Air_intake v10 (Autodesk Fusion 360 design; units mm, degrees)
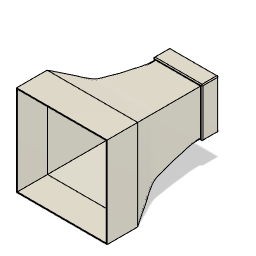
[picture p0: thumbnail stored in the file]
sketch "Sketch1" plane through (0, 0, 0) normal (0, 0, 1) x axis (1, 0, 0)
  line L1 (-150, 150) -> (150, 150)
  line L2 (-150, -150) -> (-150, 150)
  line L3 (150, -150) -> (-150, -150)
  line L4 (150, 150) -> (150, -150)
  line L5 (-150, -150) -> (150, 150)
  line L6 (150, -150) -> (-150, 150)
  point P6 (0, 0)
  point P1 (0, 0)
  point P4 (-150, -150)
  point P5 (150, -150)
  point P3 (-150, 150)
  horizontal L1
  perpendicular L1 L2
  parallel L1 L3
  parallel L2 L4
  coincident L5 P6
  coincident L6 P6
  coincident P1 P6
  dimension "d1" distance P4 P5 = 300
  dimension "d2" distance P3 P4 = 300
work_plane "WorkPlane1" AlongDistance -50
sketch "Sketch2" plane through (0, 0, -50) normal (0, 0, 1) x axis (1, 0, 0)
  line L1 (-125, 125) -> (125, 125)
  line L2 (-125, -125) -> (-125, 125)
  line L3 (125, -125) -> (-125, -125)
  line L4 (125, 125) -> (125, -125)
  line L5 (-125, -125) -> (125, 125)
  line L6 (125, -125) -> (-125, 125)
  point P6 (0, 0)
  point P1 (0, 0)
  point P4 (-125, -125)
  point P5 (125, -125)
  point P3 (-125, 125)
  horizontal L1
  perpendicular L1 L2
  parallel L1 L3
  parallel L2 L4
  coincident L5 P6
  coincident L6 P6
  coincident P1 P6
  dimension "d4" distance P4 P5 = 250
  dimension "d5" distance P3 P4 = 250
work_plane "WorkPlane2" sketch "Sketch1" AlongDistance -300
sketch "Sketch3" plane through (0, 0, -300) normal (0, 0, 1) x axis (1, 0, 0)
  line L1 (-75, 75) -> (75, 75)
  line L2 (-75, -75) -> (-75, 75)
  line L3 (75, -75) -> (-75, -75)
  line L4 (75, 75) -> (75, -75)
  line L5 (-75, -75) -> (75, 75)
  line L6 (75, -75) -> (-75, 75)
  point P6 (0, 0)
  point P1 (0, 0)
  point P4 (-75, -75)
  point P5 (75, -75)
  point P3 (-75, 75)
  horizontal L1
  perpendicular L1 L2
  parallel L1 L3
  parallel L2 L4
  coincident L5 P6
  coincident L6 P6
  coincident P1 P6
  dimension "d7" distance P4 P5 = 150
  dimension "d8" distance P3 P4 = 150
work_plane "WorkPlane3" sketch "Sketch2" AlongDistance -65
sketch "Sketch4" plane through (0, 0, -115) normal (0, 0, 1) x axis (1, 0, 0)
  line L1 (-95, 95) -> (95, 95)
  line L2 (-95, -95) -> (-95, 95)
  line L3 (95, -95) -> (-95, -95)
  line L4 (95, 95) -> (95, -95)
  line L5 (-95, -95) -> (95, 95)
  line L6 (95, -95) -> (-95, 95)
  point P6 (0, 0)
  point P1 (0, 0)
  point P4 (-95, -95)
  point P5 (95, -95)
  point P3 (-95, 95)
  horizontal L1
  perpendicular L1 L2
  parallel L1 L3
  parallel L2 L4
  coincident L5 P6
  coincident L6 P6
  coincident P1 P6
  dimension "d10" distance P4 P5 = 190
  dimension "d11" distance P3 P4 = 190
work_plane "WorkPlane4" sketch "Sketch4" AlongDistance -30
sketch "Sketch5" plane through (0, 0, -145) normal (0, 0, 1) x axis (1, 0, 0)
  line L1 (-90, 90) -> (90, 90)
  line L2 (-90, -90) -> (-90, 90)
  line L3 (90, -90) -> (-90, -90)
  line L4 (90, 90) -> (90, -90)
  line L5 (-90, -90) -> (90, 90)
  line L6 (90, -90) -> (-90, 90)
  point P6 (0, 0)
  point P1 (0, 0)
  point P4 (-90, -90)
  point P5 (90, -90)
  point P3 (-90, 90)
  horizontal L1
  perpendicular L1 L2
  parallel L1 L3
  parallel L2 L4
  coincident L5 P6
  coincident L6 P6
  coincident P1 P6
  dimension "d13" distance P4 P5 = 180
  dimension "d14" distance P3 P4 = 180
work_plane "WorkPlane5" sketch "Sketch5" AlongDistance -30
sketch "Sketch6" plane through (0, 0, -175) normal (0, 0, 1) x axis (1, 0, 0)
  line L1 (-85, 85) -> (85, 85)
  line L2 (-85, -85) -> (-85, 85)
  line L3 (85, -85) -> (-85, -85)
  line L4 (85, 85) -> (85, -85)
  line L5 (-85, -85) -> (85, 85)
  line L6 (85, -85) -> (-85, 85)
  point P6 (0, 0)
  point P1 (0, 0)
  point P4 (-85, -85)
  point P5 (85, -85)
  point P3 (-85, 85)
  horizontal L1
  perpendicular L1 L2
  parallel L1 L3
  parallel L2 L4
  coincident L5 P6
  coincident L6 P6
  coincident P1 P6
  dimension "d16" distance P4 P5 = 170
  dimension "d17" distance P3 P4 = 170
work_plane "WorkPlane6" sketch "Sketch6" AlongDistance -40
sketch "Sketch7" plane through (0, 0, -215) normal (0, 0, 1) x axis (1, 0, 0)
  line L1 (80, 80) -> (-80, 80)
  line L2 (80, -80) -> (80, 80)
  line L3 (-80, -80) -> (80, -80)
  line L4 (-80, 80) -> (-80, -80)
  line L5 (80, -80) -> (-80, 80)
  line L6 (-80, -80) -> (80, 80)
  point P6 (0, 0)
  point P1 (0, 0)
  point P4 (80, -80)
  point P5 (-80, -80)
  point P3 (80, 80)
  horizontal L1
  perpendicular L1 L2
  parallel L1 L3
  parallel L2 L4
  coincident L5 P6
  coincident L6 P6
  coincident P1 P6
  dimension "d19" distance P4 P5 = 160
  dimension "d20" distance P3 P4 = 160
work_plane "WorkPlane7" sketch "Sketch3" AlongDistance 42.5 (= "( 85 / 2 ) * 1 mm")
sketch "Sketch8" plane through (0, 0, -257.5) normal (0, 0, 1) x axis (1, 0, 0)
  line L1 (-75, 75) -> (75, 75)
  line L2 (-75, -75) -> (-75, 75)
  line L3 (75, -75) -> (-75, -75)
  line L4 (75, 75) -> (75, -75)
  line L5 (-75, -75) -> (75, 75)
  line L6 (75, -75) -> (-75, 75)
  point P6 (0, 0)
  point P1 (0, 0)
  point P4 (-75, -75)
  point P5 (75, -75)
  point P3 (-75, 75)
  horizontal L1
  perpendicular L1 L2
  parallel L1 L3
  parallel L2 L4
  coincident L5 P6
  coincident L6 P6
  coincident P1 P6
  dimension "d22" distance P4 P5 = 150
  dimension "d23" distance P3 P4 = 150
loft "Loft1" bodies "intake"
shell "Shell1" innerThickness 2
extrude "Extrude1" add of existing geometry blind 10
sketch "Sketch9" plane through (0, 0, -310) normal (0, 0, -1) x axis (-1, 0, 0)
  line L1 (-75, -75) -> (-75, 75)
  line L2 (75, -75) -> (-75, -75)
  line L3 (75, 75) -> (75, -75)
  line L4 (-75, 75) -> (75, 75)
  line L5 (-74, 74) -> (74, 74)
  line L6 (-74, -74) -> (-74, 74)
  line L7 (74, -74) -> (-74, -74)
  line L8 (74, 74) -> (74, -74)
  line L9 (-74, -74) -> (74, 74)
  line L10 (74, -74) -> (-74, 74)
  point P10 (0, 0)
  point P1 (0, 0)
  point P8 (-74, -74)
  point P9 (74, -74)
  point P7 (-74, 74)
  horizontal L5
  perpendicular L5 L6
  parallel L5 L7
  parallel L6 L8
  coincident L9 P10
  coincident L10 P10
  coincident P1 P10
  dimension "d27" distance P8 P9 = 148
  dimension "d28" distance P7 P8 = 148
extrude "Extrude2" cut sketch "Sketch9" profile of L5 L6 L7 L8 against normal blind 160
extrude "Extrude3" add of existing geometry blind 100
offset_faces "OffsetFaces1" distance 0.5
offset_faces "OffsetFaces2" distance 1.2
offset_faces "OffsetFaces3" distance 1.2
offset_faces "OffsetFaces4" distance 1.2
offset_faces "OffsetFaces5" distance 1.2
sketch "Sketch10" plane through (0, 0, 100) normal (0, 0, 1) x axis (1, 0, 0)
  line L1 (147.7485, -147.7485) -> (147.7485, 147.7485)
  line L2 (-147.7485, -147.7485) -> (147.7485, -147.7485)
  line L3 (-147.7485, 147.7485) -> (-147.7485, -147.7485)
  line L4 (147.7485, 147.7485) -> (-147.7485, 147.7485)
  line L5 (150.5, 150.5) -> (150.5, -150.5)
  line L6 (-150.5, 150.5) -> (150.5, 150.5)
  line L7 (-150.5, -150.5) -> (-150.5, 150.5)
  line L8 (150.5, -150.5) -> (-150.5, -150.5)
  line L9 (150.5, -150.5) -> (-150.5, -150.5)
  line L10 (150.5, 150.5) -> (150.5, -150.5)
  line L11 (-150.5, 150.5) -> (150.5, 150.5)
  line L12 (-150.5, -150.5) -> (-150.5, 150.5)
  line L13 (150.5, -150.5) -> (-150.5, 150.5)
  line L14 (-150.5, -150.5) -> (150.5, 150.5)
  line L15 (-156.5, 156.5) -> (156.5, 156.5)
  line L16 (-156.5, -156.5) -> (-156.5, 156.5)
  line L17 (156.5, -156.5) -> (-156.5, -156.5)
  line L18 (156.5, 156.5) -> (156.5, -156.5)
  line L19 (-156.5, -156.5) -> (156.5, 156.5)
  line L20 (156.5, -156.5) -> (-156.5, 156.5)
  point P7 (150.5, 150.5)
  point P12 (150.5, 150.5)
  point P9 (-150.5, -150.5)
  point P10 (-150.5, -150.5)
  point P8 (-150.5, 150.5)
  point P14 (-150.5, 150.5)
  point P6 (150.5, -150.5)
  point P15 (150.5, -150.5)
  point P16 (150.5, 150.5)
  point P21 (0, 0)
  point P1 (0, 0)
  horizontal L9
  vertical L10
  horizontal L11
  vertical L12
  coincident P7 P12
  coincident P9 P10
  coincident P8 P14
  coincident P6 P15
  coincident P7 P16
  horizontal L15
  perpendicular L15 L16
  parallel L15 L17
  parallel L16 L18
  coincident L19 P21
  coincident L20 P21
  coincident P1 P21
  dimension "d38" distance L11 L15 = 6
  dimension "d39" distance L12 L16 = 6
extrude "Extrude4" new body sketch "Sketch10" profile of L5 L6 L7 L8 L9 L10 L11 L12 L15 L16 L17 L18 against normal blind 6 bodies "strainer Frame"
sketch "Sketch11" plane through (0, 0, 100) normal (0, 0, 1) x axis (1, 0, 0)
  line L1 (-150.5, 150.5) -> (-150.5, -150.5)
  line L2 (150.5, 150.5) -> (-150.5, 150.5)
  line L3 (150.5, -150.5) -> (150.5, 150.5)
  line L4 (-150.5, -150.5) -> (150.5, -150.5)
  line L5 (156.5, 156.5) -> (156.5, -156.5)
  line L6 (-156.5, 156.5) -> (156.5, 156.5)
  line L7 (-156.5, -156.5) -> (-156.5, 156.5)
  line L8 (156.5, -156.5) -> (-156.5, -156.5)
  line L9 (-144.5, 144.5) -> (144.5, 144.5)
  line L10 (-144.5, -144.5) -> (-144.5, 144.5)
  line L11 (144.5, -144.5) -> (-144.5, -144.5)
  line L12 (144.5, 144.5) -> (144.5, -144.5)
  line L13 (-144.5, -144.5) -> (144.5, 144.5)
  line L14 (144.5, -144.5) -> (-144.5, 144.5)
  line L15 (-156.5, 156.5) -> (156.5, 156.5)
  line L16 (-156.5, -156.5) -> (-156.5, 156.5)
  line L17 (156.5, -156.5) -> (-156.5, -156.5)
  line L18 (156.5, 156.5) -> (156.5, -156.5)
  line L19 (-156.5, -156.5) -> (156.5, 156.5)
  line L20 (156.5, -156.5) -> (-156.5, 156.5)
  point P14 (0, 0)
  point P1 (0, 0)
  point P19 (0, 0)
  point P7 (156.5, 156.5)
  point P15 (156.5, 156.5)
  horizontal L9
  perpendicular L9 L10
  parallel L9 L11
  parallel L10 L12
  coincident L13 P14
  coincident L14 P14
  coincident P1 P14
  horizontal L15
  perpendicular L15 L16
  parallel L15 L17
  parallel L16 L18
  coincident L19 P19
  coincident L20 P19
  coincident P7 P15
  coincident P14 P19
  dimension "d42" distance L6 L9 = 12
  dimension "d43" distance L7 L10 = 12
extrude "Extrude5" add sketch "Sketch11" profile of L1 L2 L3 L4 L5 L6 L7 L8 L9 L10 L11 L12 L15 L16 L17 L18 along normal blind 6
sketch "Sketch13" plane through (0, 0, -310) normal (0, 0, -1) x axis (-1, 0, 0)
  line L1 (74, 74) -> (-74, 74)
  line L2 (74, -74) -> (74, 74)
  line L3 (-74, -74) -> (74, -74)
  line L4 (-74, 74) -> (-74, -74)
  line L5 (-76.2, -76.2) -> (-76.2, 76.2)
  line L6 (76.2, -76.2) -> (-76.2, -76.2)
  line L7 (76.2, 76.2) -> (76.2, -76.2)
  line L8 (-76.2, 76.2) -> (76.2, 76.2)
  line L9 (76.2, 76.2) -> (-76.2, 76.2)
  line L10 (76.2, -76.2) -> (76.2, 76.2)
  line L11 (-76.2, -76.2) -> (76.2, -76.2)
  line L12 (-76.2, 76.2) -> (-76.2, -76.2)
  line L13 (-81.2, 81.2) -> (81.2, 81.2)
  line L14 (-81.2, -81.2) -> (-81.2, 81.2)
  line L15 (81.2, -81.2) -> (-81.2, -81.2)
  line L16 (81.2, 81.2) -> (81.2, -81.2)
  line L17 (-81.2, -81.2) -> (81.2, 81.2)
  line L18 (81.2, -81.2) -> (-81.2, 81.2)
  point P8 (76.2, -76.2)
  point P12 (76.2, -76.2)
  point P6 (-76.2, 76.2)
  point P10 (-76.2, 76.2)
  point P18 (0, 0)
  point P1 (0, 0)
  horizontal L9
  vertical L10
  horizontal L11
  vertical L12
  coincident P8 P12
  coincident P6 P10
  horizontal L13
  perpendicular L13 L14
  parallel L13 L15
  parallel L14 L16
  coincident L17 P18
  coincident L18 P18
  coincident P1 P18
  dimension "d46" distance L9 L13 = 5
  dimension "d47" distance L10 L16 = 5
extrude "Extrude6" new body sketch "Sketch13" profile of L5 L6 L7 L8 L9 L10 L11 L12 L13 L14 L15 L16 against normal blind 25
sketch "Sketch14" plane through (0, 0, -310) normal (0, 0, -1) x axis (-1, 0, 0)
  line L1 (-76.2, -76.2) -> (76.2, -76.2)
  line L2 (-76.2, 76.2) -> (-76.2, -76.2)
  line L3 (76.2, 76.2) -> (-76.2, 76.2)
  line L4 (76.2, -76.2) -> (76.2, 76.2)
  line L5 (81.2, 81.2) -> (81.2, -81.2)
  line L6 (-81.2, 81.2) -> (81.2, 81.2)
  line L7 (-81.2, -81.2) -> (-81.2, 81.2)
  line L8 (81.2, -81.2) -> (-81.2, -81.2)
  line L9 (-75.25, 75.25) -> (75.25, 75.25)
  line L10 (-75.25, -75.25) -> (-75.25, 75.25)
  line L11 (75.25, -75.25) -> (-75.25, -75.25)
  line L12 (75.25, 75.25) -> (75.25, -75.25)
  line L13 (-75.25, -75.25) -> (75.25, 75.25)
  line L14 (75.25, -75.25) -> (-75.25, 75.25)
  line L15 (-81.2, 81.2) -> (81.2, 81.2)
  line L16 (-81.2, -81.2) -> (-81.2, 81.2)
  line L17 (81.2, -81.2) -> (-81.2, -81.2)
  line L18 (81.2, 81.2) -> (81.2, -81.2)
  line L19 (-81.2, -81.2) -> (81.2, 81.2)
  line L20 (81.2, -81.2) -> (-81.2, 81.2)
  point P14 (0, 0)
  point P1 (0, 0)
  point P19 (0, 0)
  point P7 (81.2, 81.2)
  point P15 (81.2, 81.2)
  point P11 (-75.25, 75.25)
  point P12 (-75.25, -75.25)
  point P13 (75.25, -75.25)
  horizontal L9
  perpendicular L9 L10
  parallel L9 L11
  parallel L10 L12
  coincident L13 P14
  coincident L14 P14
  coincident P1 P14
  horizontal L15
  perpendicular L15 L16
  parallel L15 L17
  parallel L16 L18
  coincident L19 P19
  coincident L20 P19
  coincident P7 P15
  coincident P1 P19
  dimension "d50" distance P11 P12 = 150.5
  dimension "d51" distance P12 P13 = 150.5
extrude "Extrude7" add sketch "Sketch14" profile of L1 L2 L3 L4 L5 L6 L7 L8 L9 L10 L11 L12 L15 L16 L17 L18 along normal blind 30
fillet "Fillet1" radius 3
named bodies: "intake", "strainer Frame"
